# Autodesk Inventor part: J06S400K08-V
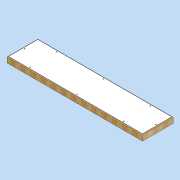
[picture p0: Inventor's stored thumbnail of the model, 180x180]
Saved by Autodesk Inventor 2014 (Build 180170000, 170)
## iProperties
Created: 2011-04
Part Number: J06S400K08-V
Document SubType Name: Modeling
Designer: david.appleford
Density: 1 g/cm^3
Description: Joist 1.5w x 400mm - Locks 8
Mass: 55661 g
Surface Area: 17606.3 cm^2
Volume: 55661 cm^3
Cost Center: £70.00
Material: Generic
Appearance: Wood (Pine)
Justset: False
Title: Panel 0.5w x 1w Locks 3
Author: david.appleford
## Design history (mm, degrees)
sketch "Sketch1"
  geometry: L1 (0, 0)-(1830, 0); L2 (1830, 0)-(1830, 468); L3 (1830, 468)-(0, 468); L4 (0, 468)-(0, 0); L5 (34, 434)-(1796, 434); L6 (1796, 434)-(1796, 34); L7 (1796, 34)-(34, 34); L8 (34, 34)-(34, 434)
  constraints: 16 end point, 4 parallel, 2 perpendicular, 1 horizontal, 3 other
  dimensions: "d0" = 1830 distance between parallel lines of L2 L4; "d1" = 468 distance between parallel lines of L1 L3; "d2" = 34 distance between parallel lines of L5 L3 (= 0.5 x t); "d30" = 400 distance between parallel lines of L7 L5 (derived); "d31" = 1762 distance between parallel lines of L6 L8 (derived)
extrude "Extrusion1" new body sketch "Sketch1" distance "d3" = 68 (= t); taper "d4" = 0 deg
sketch "Sketch2"
  geometry: L1 (1796, 434)-(1796, 34) reference; L2 (34, 434)-(1796, 434) reference; L3 (34, 34)-(34, 434) reference; L4 (1796, 34)-(34, 34) reference; L5 (1786, 424)-(1786, 44); L6 (1786, 44)-(44, 44); L7 (44, 44)-(44, 424); L8 (44, 424)-(1786, 424); 1 further point
  constraints: 8 end point, 3 other
  dimensions: "d5" = 10 distance between parallel lines of L8 L2
extrude "Extrusion2" join sketch "Sketch2" distance "d6" = 6 (= sw); taper "d7" = 0 deg
sketch "Sketch3"
  geometry: L1 (-44, 424)-(-1786, 424) reference; L2 (-1786, 424)-(-1786, 44) reference; L3 (-44, 44)-(-44, 424) reference; L4 (-1786, 44)-(-44, 44) reference; 1 further point
extrude "Extrusion3" join sketch "Sketch3" distance "d8" = 6 (= sw); taper "d9" = 0 deg
sketch "Sketch4"
  geometry: L1 (34, 434)-(1796, 434) reference; L2 (1796, 434)-(1796, 34) reference; L3 (1796, 34)-(34, 34) reference; L4 (34, 34)-(34, 434) reference; 9 further points
  constraints: 5 horizontal alignment, 3 vertical alignment
  dimensions: "d10" = 28 distance from line of point (305, 406) L1 (= k); "d12" = 28 distance from line of L3 point (915, 62) (= k); "d13" = 28 distance from line of point (62, 234) L4 (= k); "d14" = 305 horizontal distance of point (305, 406) point (0, 0) (= 0.25 x w); "d15" = 610 horizontal distance of point (915, 62) point (305, 406) (= 0.5 x w); "d29" = 28 distance from line of L2 point (1768, 234) (= d13); "d32" = 400 distance between parallel lines of L3 L1 (derived); "d33" = 200 distance from line of L1 point (62, 234) (= 0.5 x d32); "d36" = 1220 distance of point (305, 406) point (1525, 406)
hole "Hole1" sketch "Sketch4" at (305, 406), (62, 234), (915, 62), (1768, 234), (915, 406), (305, 62), (1525, 406), (1525, 62) diameter "d22" = 12 (= hd); stored, may be unused: countersink angle "d26" = 90 deg, drill point angle "d28" = 118 deg; dims "d23" = 6, "d24" = 4, "d25" = 2, "d27" = 8
sketch "Sketch5"
  geometry: L1 (-1796, 34)-(-34, 34) reference; L2 (-34, 434)-(-1796, 434) reference; L3 (-1176, 34)-(-1264, 34); L4 (-1264, 34)-(-1264, 434); L5 (-1264, 434)-(-1176, 434); L6 (-1176, 434)-(-1176, 34); L7 (-1220, 34)-(-1220, 434); 1 further point
  constraints: 10 end point, 2 midpoint, 2 point on line
  dimensions: "d41" = 1220 distance from line of L7 point (0, 0); "d42" = 88 distance between parallel lines of L4 L6
extrude "Extrusion4" cut sketch "Sketch5" stored distance "d43" = 10; taper "d44" = 0 deg
body "Solid1"
node "Projected Loop1"
other parameters: "t" = 68 [user parameter; used in 2 equation terms], "e" = 16 [user parameter], "sw" = 6 [user parameter; used in 2 equation terms], "sc" = 9 [user parameter], "sf" = 12 [user parameter], "k" = 28 [user parameter; used in 3 equation terms], "hd" = 12 [user parameter; used in 1 equation term]
